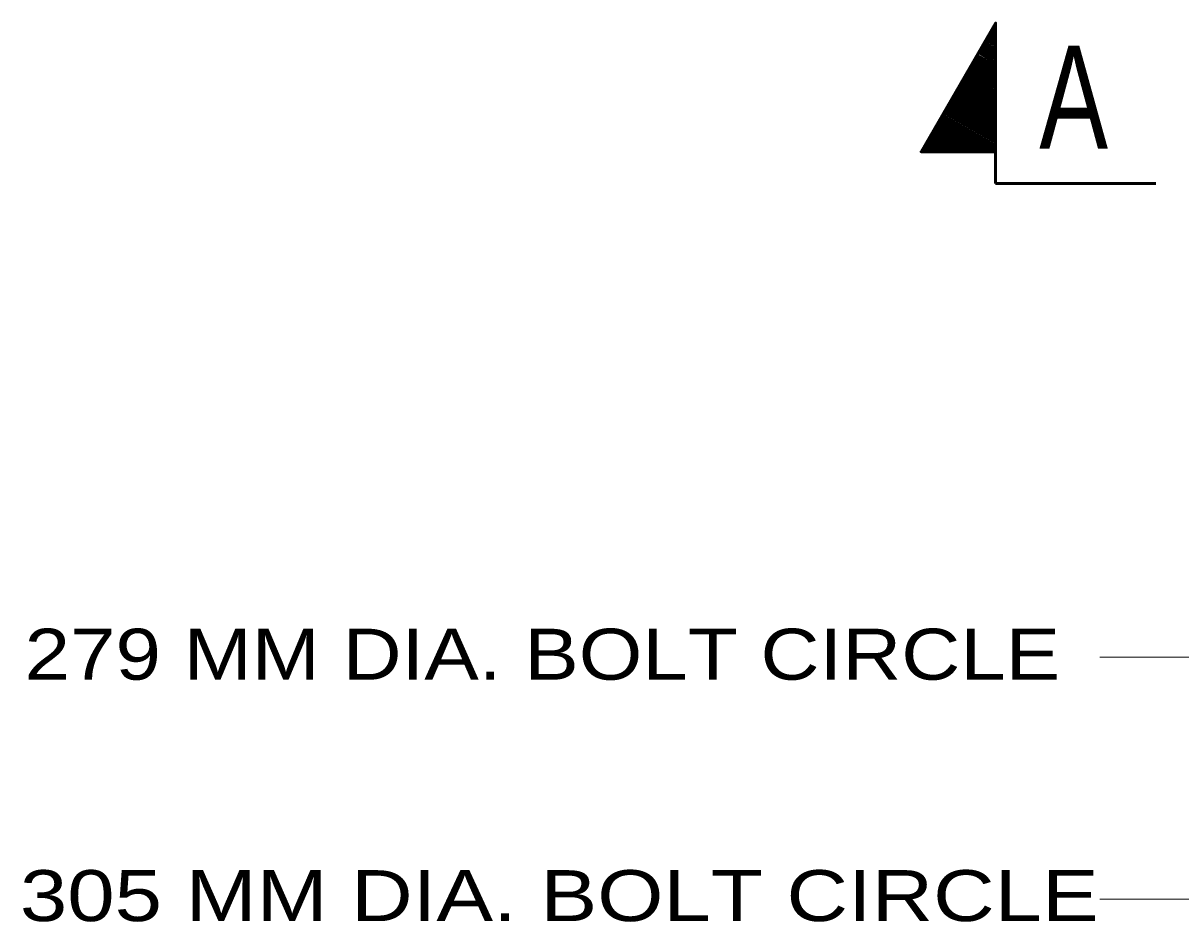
# Model space of a CAD drawing. Extents: x 312583 to 312854, y 144419 to 144597.
# Drawn here: x 312662.57 to 312679.84, y 144503.15 to 144516.56 of the extents above; entities that cross this region are included whole.
import ezdxf
from ezdxf.enums import TextEntityAlignment as Align

# ---------------------------------------------------------------- set-up
doc = ezdxf.new("R2010")
doc.units = 0
doc.header["$LTSCALE"] = 0.3
doc.layers.add('2', color=7, linetype='Continuous', lineweight=13)

msp = doc.modelspace()

# ---------------------------------------------------------------- linework, layer by layer
at = {"layer": '2', "lineweight": 35}
for p, q in [((312677.0771, 144516.54), (312677.0618, 144516.54)), ((312677.0771, 144516.287), (312676.9621, 144516.356)), ((312677.0771, 144516.31), (312676.9698, 144516.379)), ((312677.0771, 144516.3406), (312676.9851, 144516.3943)), ((312677.0771, 144516.3713), (312676.9928, 144516.4173)), ((312677.0771, 144516.402), (312677.0081, 144516.4403)), ((312677.0771, 144516.425), (312677.0158, 144516.4556)), ((312677.0771, 144516.4556), (312677.0311, 144516.4786)), ((312677.0771, 144516.4786), (312677.0388, 144516.5016)), ((312677.0771, 144516.5093), (312677.0541, 144516.517)), ((312677.0771, 144516.0646), (312676.8625, 144516.1873)), ((312677.0771, 144516.0953), (312676.8701, 144516.2103)), ((312677.0771, 144516.1183), (312676.8855, 144516.2333)), ((312677.0771, 144516.149), (312676.9008, 144516.2486)), ((312677.0771, 144516.1796), (312676.9085, 144516.2716)), ((312677.0771, 144516.2103), (312676.9238, 144516.2946)), ((312677.0771, 144516.2333), (312676.9391, 144516.31)), ((312677.0771, 144516.264), (312676.9468, 144516.333)), ((312677.0771, 144515.8423), (312676.7705, 144516.0186)), ((312677.0771, 144515.873), (312676.7781, 144516.0416)), ((312677.0771, 144515.9036), (312676.7935, 144516.0646)), ((312677.0771, 144515.9266), (312676.8011, 144516.08)), ((312677.0771, 144515.9573), (312676.8165, 144516.1106)), ((312677.0771, 144515.9803), (312676.8241, 144516.126)), ((312677.0771, 144516.011), (312676.8395, 144516.149)), ((312677.0771, 144516.0416), (312676.8471, 144516.172)), ((312677.0771, 144515.597), (312676.6555, 144515.8346)), ((312677.0771, 144515.62), (312676.6708, 144515.8576)), ((312677.0771, 144515.6506), (312676.6785, 144515.8806)), ((312677.0771, 144515.6813), (312676.6938, 144515.896)), ((312677.0771, 144515.712), (312676.7091, 144515.919)), ((312677.0771, 144515.735), (312676.7168, 144515.942)), ((312677.0771, 144515.7656), (312676.7321, 144515.9573)), ((312677.0771, 144515.7886), (312676.7475, 144515.9803)), ((312677.0771, 144515.8193), (312676.7551, 144516.0033)), ((312677.0771, 144515.3746), (312676.5635, 144515.6736)), ((312677.0771, 144515.4053), (312676.5788, 144515.689)), ((312677.0771, 144515.4283), (312676.5865, 144515.712)), ((312677.0771, 144515.459), (312676.6018, 144515.735)), ((312677.0771, 144515.4896), (312676.6095, 144515.7503)), ((312677.0771, 144515.5126), (312676.6248, 144515.7733)), ((312677.0771, 144515.5433), (312676.6325, 144515.7963)), ((312677.0771, 144515.574), (312676.6478, 144515.8116)), ((312677.0771, 144515.1523), (312676.4715, 144515.505)), ((312677.0771, 144515.183), (312676.4791, 144515.5203)), ((312677.0771, 144515.2136), (312676.4945, 144515.5433)), ((312677.0771, 144515.2366), (312676.5021, 144515.5663)), ((312677.0771, 144515.2673), (312676.5175, 144515.5816)), ((312677.0695, 144515.2903), (312676.5251, 144515.6123)), ((312677.0771, 144515.321), (312676.5405, 144515.6276)), ((312677.0771, 144515.344), (312676.5558, 144515.6506)), ((312677.0771, 144514.907), (312676.3641, 144515.3133)), ((312677.0771, 144514.93), (312676.3718, 144515.3363)), ((312677.0771, 144514.9606), (312676.3871, 144515.3593)), ((312677.0771, 144514.9913), (312676.4025, 144515.3823)), ((312677.0771, 144515.0143), (312676.4101, 144515.3976)), ((312677.0695, 144515.045), (312676.4255, 144515.4206)), ((312677.0771, 144515.0756), (312676.4331, 144515.4436)), ((312677.0771, 144515.0986), (312676.4485, 144515.459)), ((312677.0771, 144515.1216), (312676.4561, 144515.482)), ((312677.0771, 144514.6846), (312676.2645, 144515.1523)), ((312677.0771, 144514.7153), (312676.2798, 144515.1753)), ((312677.0771, 144514.7383), (312676.2875, 144515.1906)), ((312677.0771, 144514.769), (312676.3028, 144515.2136)), ((312677.0695, 144514.792), (312676.3105, 144515.2366)), ((312677.0695, 144514.8226), (312676.3258, 144515.252)), ((312677.0771, 144514.8456), (312676.3335, 144515.275)), ((312677.0771, 144514.8763), (312676.3488, 144515.298)), ((312676.7705, 144514.6386), (312676.1725, 144514.9836)), ((312676.8165, 144514.6386), (312676.1801, 144515.0066)), ((312676.8625, 144514.6386), (312676.1955, 144515.022)), ((312676.9085, 144514.6386), (312676.2108, 144515.045)), ((312676.9621, 144514.6386), (312676.2185, 144515.068)), ((312677.0005, 144514.6386), (312676.2338, 144515.0833)), ((312677.0541, 144514.6386), (312676.2415, 144515.114)), ((312677.0771, 144514.654), (312676.2568, 144515.1293)), ((312676.3335, 144514.6386), (312676.0651, 144514.7996)), ((312676.3795, 144514.6386), (312676.0728, 144514.815)), ((312676.4255, 144514.6386), (312676.0881, 144514.8456)), ((312676.4791, 144514.6386), (312676.0958, 144514.861)), ((312676.5251, 144514.6386), (312676.1111, 144514.884)), ((312676.5711, 144514.6386), (312676.1188, 144514.907)), ((312676.6248, 144514.6386), (312676.1341, 144514.9223)), ((312676.6708, 144514.6386), (312676.1418, 144514.9453)), ((312676.7168, 144514.6386), (312676.1571, 144514.9606)), ((312675.9961, 144514.6386), (312675.9808, 144514.654)), ((312676.0421, 144514.6386), (312675.9885, 144514.677)), ((312676.0958, 144514.6386), (312676.0038, 144514.6923)), ((312676.1418, 144514.6386), (312676.0191, 144514.7153)), ((312676.1955, 144514.6386), (312676.0268, 144514.7383)), ((312676.2338, 144514.6386), (312676.0421, 144514.7536)), ((312676.2875, 144514.6386), (312676.0498, 144514.7766))]:
    msp.add_line(p, q, dxfattribs=at)
at = {"layer": '2', "lineweight": 53}
for p in [(312677.0771, 144514.6386), (312679.4691, 144514.1633)]:
    msp.add_line(p, (312677.0771, 144514.1633), dxfattribs=at)
at = {"layer": '2'}
for p, q in [((312681.7845, 144507.1023), (312678.6335, 144507.1023)), ((312684.8741, 144503.4913), (312678.6335, 144503.4913))]:
    msp.add_line(p, q, dxfattribs=at)
at = {"layer": '2', "lineweight": 53}
msp.add_lwpolyline([(312677.0771, 144514.6386), (312675.9655, 144514.6386), (312677.0771, 144516.5553)], close=True, dxfattribs=at)

# ---------------------------------------------------------------- texts
at = {"layer": '2', "width": 0.75}
msp.add_text('A', height=1.533, dxfattribs=at).set_placement((312678.2424, 144514.6846), align=Align.CENTER)
at = {"layer": '2'}
for s, width, p in [('279 MM DIA. BOLT CIRCLE', 1.2, (312662.5912, 144506.765)), ('305 MM DIA. BOLT CIRCLE', 1.25, (312662.5219, 144503.1646))]:
    msp.add_text(s, height=0.76, dxfattribs=dict(at, width=width)).set_placement(p)

doc.saveas('drawing.dxf')
